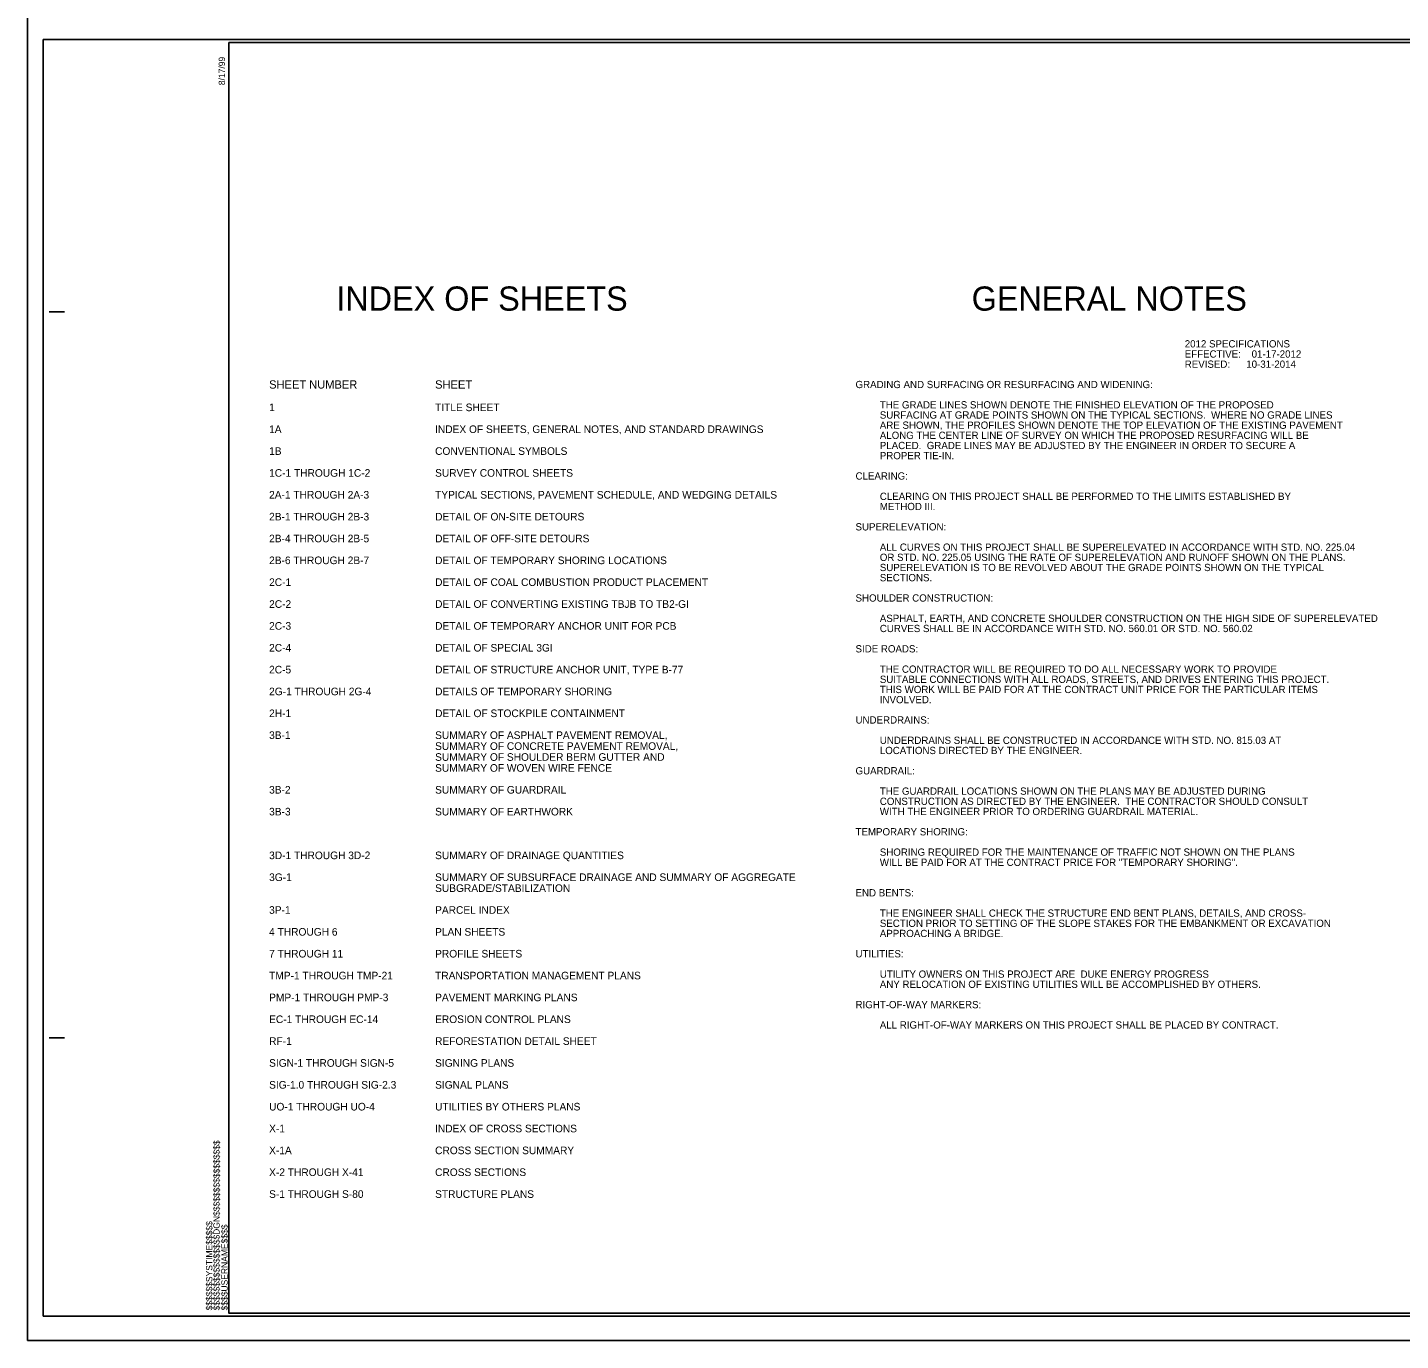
# Model space of a CAD drawing. Extents: x 2241278 to 2254132, y 649924 to 670434.
# Drawn here: x 2244559 to 2250231, y 649924 to 655349 of the extents above; entities that cross this region are included whole.
import ezdxf

# ---------------------------------------------------------------- set-up
doc = ezdxf.new("R2010")
doc.units = 0
for name, color, linetype in [('Sheet Cutting Line CELL', 7, 'Continuous'), ('Sheet Data Text CELL', 7, 'Continuous'), ('Sheet Plan CELL', 7, 'Continuous'), ('Sheet Plot Border Inside CELL', 7, 'Continuous'), ('Sheet Plot Border Outside CELL', 7, 'Continuous')]:
    doc.layers.add(name, color=color, linetype=linetype)

msp = doc.modelspace()

# ---------------------------------------------------------------- linework, layer by layer
at = {"layer": 'Sheet Cutting Line CELL'}
for p, q in [((2244558.8, 655399.2), (2244558.8, 649924.2)), ((2244558.8, 649924.2), (2252976.3, 649924.2))]:
    msp.add_line(p, q, dxfattribs=at)
at = {"layer": 'Sheet Plan CELL'}
for p, q in [((2245391.3, 655286.7), (2245391.3, 655286.7)), ((2244648.8, 654174.2), (2244711.3, 654174.2)), ((2244648.8, 651174.2), (2244711.3, 651174.2)), ((2245391.3, 650036.7), (2245391.3, 650036.7))]:
    msp.add_line(p, q, dxfattribs=at)
msp.add_lwpolyline([(2252891.3, 655286.7), (2245391.3, 655286.7), (2245391.3, 650036.7), (2252891.3, 650036.7)], close=True, dxfattribs=at)
at = {"layer": 'Sheet Plot Border Inside CELL'}
msp.add_lwpolyline([(2244623.8, 650024.2), (2252953.8, 650024.2), (2252953.8, 655299.2), (2244623.8, 655299.2)], close=True, dxfattribs=at)
at = {"layer": 'Sheet Plot Border Outside CELL'}
msp.add_lwpolyline([(2244558.8, 649924.2), (2252976.3, 649924.2), (2252976.3, 655399.2), (2244558.8, 655399.2)], close=True, dxfattribs=at)

# ---------------------------------------------------------------- texts
at = {"layer": 'Sheet Data Text CELL'}
for s, height, p in [('INDEX OF SHEETS', 100, (2245834.7, 654179.1)), ('GENERAL NOTES', 100, (2248459.5, 654179.1)), ('2012 SPECIFICATIONS', 30, (2249339.7, 654027.1)), ('EFFECTIVE:    01-17-2012', 30, (2249339.7, 653985.1)), ('REVISED:      10-31-2014', 30, (2249339.7, 653943.1)), ('SHEET NUMBER', 34.286, (2245557.1, 653857)), ('SHEET', 34.29, (2246242.8, 653857)), ('GRADING AND SURFACING OR RESURFACING AND WIDENING:  ', 30, (2247979.7, 653859.1)), ('         THE GRADE LINES SHOWN DENOTE THE FINISHED ELEVATION OF THE PROPOSED ', 30, (2247979.7, 653775.1)), ('1', 31.4, (2245557.1, 653763.9)), ('TITLE SHEET', 31.429, (2246242.8, 653763.9)), ('         SURFACING AT GRADE POINTS SHOWN ON THE TYPICAL SECTIONS.  WHERE NO GRADE LINES ', 30, (2247979.7, 653733.1)), ('1A', 31.43, (2245557.1, 653673.6)), ('INDEX OF SHEETS, GENERAL NOTES, AND STANDARD DRAWINGS', 31.429, (2246242.8, 653673.6)), ('         ARE SHOWN, THE PROFILES SHOWN DENOTE THE TOP ELEVATION OF THE EXISTING PAVEMENT ', 30, (2247979.7, 653691.1)), ('         ALONG THE CENTER LINE OF SURVEY ON WHICH THE PROPOSED RESURFACING WILL BE ', 30, (2247979.7, 653649.1)), ('         PLACED.  GRADE LINES MAY BE ADJUSTED BY THE ENGINEER IN ORDER TO SECURE A ', 30, (2247979.7, 653607.1)), ('1B', 31.43, (2245557.1, 653583.3)), ('CONVENTIONAL SYMBOLS', 31.429, (2246242.8, 653583.3)), ('         PROPER TIE-IN.  ', 30, (2247979.7, 653565.1)), ('1C-1 THROUGH 1C-2', 31.429, (2245557.1, 653493)), ('SURVEY CONTROL SHEETS', 31.429, (2246242.8, 653493)), ('CLEARING:  ', 30, (2247979.7, 653481.1)), ('2A-1 THROUGH 2A-3', 31.429, (2245557.1, 653402.7)), ('TYPICAL SECTIONS, PAVEMENT SCHEDULE, AND WEDGING DETAILS', 31.429, (2246242.8, 653402.7)), ('         CLEARING ON THIS PROJECT SHALL BE PERFORMED TO THE LIMITS ESTABLISHED BY ', 30, (2247979.7, 653397.1)), ('         METHOD III.', 30, (2247979.7, 653355.1)), ('2B-1 THROUGH 2B-3', 31.429, (2245557.1, 653312.4)), ('DETAIL OF ON-SITE DETOURS', 31.429, (2246242.8, 653312.4)), ('SUPERELEVATION:  ', 30, (2247979.7, 653271.1)), ('2B-4 THROUGH 2B-5', 31.429, (2245557.1, 653222.1)), ('DETAIL OF OFF-SITE DETOURS', 31.429, (2246242.8, 653222.1)), ('         ALL CURVES ON THIS PROJECT SHALL BE SUPERELEVATED IN ACCORDANCE WITH STD. NO. 225.04', 30, (2247979.7, 653187.1)), ('2B-6 THROUGH 2B-7', 31.429, (2245557.1, 653131.9)), ('DETAIL OF TEMPORARY SHORING LOCATIONS', 31.429, (2246242.8, 653131.9)), ('         SUPERELEVATION IS TO BE REVOLVED ABOUT THE GRADE POINTS SHOWN ON THE TYPICAL ', 30, (2247979.7, 653103.1)), ('         OR STD. NO. 225.05 USING THE RATE OF SUPERELEVATION AND RUNOFF SHOWN ON THE PLANS.', 30, (2247979.7, 653145.1)), ('2C-1', 31.43, (2245557.1, 653041.6)), ('DETAIL OF COAL COMBUSTION PRODUCT PLACEMENT', 31.429, (2246242.8, 653041.6)), ('         SECTIONS.  ', 30, (2247979.7, 653061.1)), ('2C-2', 31.43, (2245557.1, 652951.3)), ('DETAIL OF CONVERTING EXISTING TBJB TO TB2-GI', 31.429, (2246242.8, 652951.3)), ('SHOULDER CONSTRUCTION:  ', 30, (2247979.7, 652977.1)), ('         ASPHALT, EARTH, AND CONCRETE SHOULDER CONSTRUCTION ON THE HIGH SIDE OF SUPERELEVATED ', 30, (2247979.7, 652893.1)), ('2C-3', 31.43, (2245557.1, 652861)), ('DETAIL OF TEMPORARY ANCHOR UNIT FOR PCB', 31.429, (2246242.8, 652861)), ('         CURVES SHALL BE IN ACCORDANCE WITH STD. NO. 560.01 OR STD. NO. 560.02', 30, (2247979.7, 652851.1)), ('2C-4', 31.43, (2245557.1, 652770.7)), ('DETAIL OF SPECIAL 3GI', 31.429, (2246242.8, 652770.7)), ('SIDE ROADS:  ', 30, (2247979.7, 652767.1)), ('2C-5', 31.43, (2245557.1, 652680.4)), ('DETAIL OF STRUCTURE ANCHOR UNIT, TYPE B-77', 31.429, (2246242.8, 652680.4)), ('         THE CONTRACTOR WILL BE REQUIRED TO DO ALL NECESSARY WORK TO PROVIDE ', 30, (2247979.7, 652683.1)), ('         SUITABLE CONNECTIONS WITH ALL ROADS, STREETS, AND DRIVES ENTERING THIS PROJECT.  ', 30, (2247979.7, 652641.1)), ('2G-1 THROUGH 2G-4', 31.429, (2245557.1, 652590.1)), ('DETAILS OF TEMPORARY SHORING', 31.429, (2246242.8, 652590.1)), ('         THIS WORK WILL BE PAID FOR AT THE CONTRACT UNIT PRICE FOR THE PARTICULAR ITEMS ', 30, (2247979.7, 652599.1)), ('         INVOLVED.  ', 30, (2247979.7, 652557.1)), ('2H-1', 31.43, (2245557.1, 652499.9)), ('DETAIL OF STOCKPILE CONTAINMENT', 31.429, (2246242.8, 652499.9)), ('UNDERDRAINS:  ', 30, (2247979.7, 652473.1)), ('3B-1', 31.43, (2245557.1, 652409.6)), ('SUMMARY OF ASPHALT PAVEMENT REMOVAL,', 31.429, (2246242.8, 652409.6)), ('SUMMARY OF CONCRETE PAVEMENT REMOVAL,', 31.429, (2246242.8, 652364.4)), ('         UNDERDRAINS SHALL BE CONSTRUCTED IN ACCORDANCE WITH STD. NO. 815.03 AT ', 30, (2247979.7, 652389.1)), ('SUMMARY OF SHOULDER BERM GUTTER AND', 31.429, (2246242.8, 652319.3)), ('         LOCATIONS DIRECTED BY THE ENGINEER.  ', 30, (2247979.7, 652347.1)), ('SUMMARY OF WOVEN WIRE FENCE', 31.429, (2246242.8, 652274.1)), ('GUARDRAIL:  ', 30, (2247979.7, 652263.1)), ('3B-2', 31.43, (2245557.1, 652183.9)), ('SUMMARY OF GUARDRAIL', 31.429, (2246242.8, 652183.9)), ('         THE GUARDRAIL LOCATIONS SHOWN ON THE PLANS MAY BE ADJUSTED DURING ', 30, (2247979.7, 652179.1)), ('         CONSTRUCTION AS DIRECTED BY THE ENGINEER.  THE CONTRACTOR SHOULD CONSULT', 30, (2247979.7, 652137.1)), ('3B-3', 31.43, (2245557.1, 652093.6)), ('SUMMARY OF EARTHWORK', 31.429, (2246242.8, 652093.6)), ('         WITH THE ENGINEER PRIOR TO ORDERING GUARDRAIL MATERIAL.', 30, (2247979.7, 652095.1)), ('TEMPORARY SHORING:  ', 30, (2247979.7, 652011.1)), ('3D-1 THROUGH 3D-2', 31.429, (2245557.1, 651913)), ('SUMMARY OF DRAINAGE QUANTITIES', 31.429, (2246242.8, 651913)), ('         SHORING REQUIRED FOR THE MAINTENANCE OF TRAFFIC NOT SHOWN ON THE PLANS ', 30, (2247979.7, 651927.1)), ('         WILL BE PAID FOR AT THE CONTRACT PRICE FOR "TEMPORARY SHORING".', 30, (2247979.7, 651885.1)), ('3G-1', 31.43, (2245557.1, 651822.7)), ('SUMMARY OF SUBSURFACE DRAINAGE AND SUMMARY OF AGGREGATE', 31.429, (2246242.8, 651822.7)), ('SUBGRADE/STABILIZATION', 31.429, (2246242.8, 651777.6)), ('END BENTS:  ', 30, (2247979.7, 651759.1)), ('3P-1', 31.43, (2245557.1, 651687.3)), ('PARCEL INDEX', 31.429, (2246242.8, 651687.3)), ('         THE ENGINEER SHALL CHECK THE STRUCTURE END BENT PLANS, DETAILS, AND CROSS-', 30, (2247979.7, 651675.1)), ('         SECTION PRIOR TO SETTING OF THE SLOPE STAKES FOR THE EMBANKMENT OR EXCAVATION ', 30, (2247979.7, 651633.1)), ('4 THROUGH 6', 31.429, (2245557.1, 651597)), ('PLAN SHEETS', 31.429, (2246242.8, 651597)), ('         APPROACHING A BRIDGE.  ', 30, (2247979.7, 651591.1)), ('7 THROUGH 11 ', 31.429, (2245557.1, 651506.7)), ('PROFILE SHEETS', 31.429, (2246242.8, 651506.7)), ('UTILITIES:  ', 30, (2247979.7, 651507.1)), ('TMP-1 THROUGH TMP-21', 31.429, (2245557.1, 651416.4)), ('TRANSPORTATION MANAGEMENT PLANS', 31.429, (2246242.8, 651416.4)), ('         UTILITY OWNERS ON THIS PROJECT ARE  DUKE ENERGY PROGRESS', 30, (2247979.7, 651423.1)), ('         ANY RELOCATION OF EXISTING UTILITIES WILL BE ACCOMPLISHED BY OTHERS.  ', 30, (2247979.7, 651381.1)), ('PMP-1 THROUGH PMP-3', 31.429, (2245557.1, 651326.1)), ('PAVEMENT MARKING PLANS', 31.429, (2246242.8, 651326.1)), ('RIGHT-OF-WAY MARKERS:  ', 30, (2247979.7, 651297.1)), ('EC-1 THROUGH EC-14', 31.429, (2245557.1, 651235.9)), ('EROSION CONTROL PLANS', 31.429, (2246242.8, 651235.9)), ('         ALL RIGHT-OF-WAY MARKERS ON THIS PROJECT SHALL BE PLACED BY CONTRACT.  ', 30, (2247979.7, 651213.1)), ('RF-1', 31.43, (2245557.1, 651145.6)), ('REFORESTATION DETAIL SHEET', 31.429, (2246242.8, 651145.6)), ('SIGN-1 THROUGH SIGN-5', 31.429, (2245557.1, 651055.3)), ('SIGNING PLANS', 31.429, (2246242.8, 651055.3)), ('SIG-1.0 THROUGH SIG-2.3', 31.429, (2245557.1, 650965)), ('SIGNAL PLANS', 31.429, (2246242.8, 650965)), ('UO-1 THROUGH UO-4', 31.429, (2245557.1, 650874.7)), ('UTILITIES BY OTHERS PLANS', 31.429, (2246242.8, 650874.7)), ('X-1', 31.43, (2245557.1, 650784.4)), ('INDEX OF CROSS SECTIONS', 31.429, (2246242.8, 650784.4)), ('X-1A', 31.43, (2245557.1, 650694.1)), ('CROSS SECTION SUMMARY', 31.429, (2246242.8, 650694.1)), ('X-2 THROUGH X-41', 31.429, (2245557.1, 650603.9)), ('CROSS SECTIONS', 31.429, (2246242.8, 650603.9)), ('S-1 THROUGH S-80', 31.429, (2245557.1, 650513.6)), ('STRUCTURE PLANS', 31.429, (2246242.8, 650513.6))]:
    msp.add_text(s, height=height, dxfattribs=at).set_placement(p)
at = {"layer": 'Sheet Plan CELL'}
for s, p in [('8/17/99', (2245375, 655110.7)), ('$$$$$$$$$$$$$$$$DGN$$$$$$$$$$$$$$$$', (2245353, 650048.5)), ('$$$$$$SYSTIME$$$$$', (2245322.8, 650048.5)), ('$$$$USERNAME$$$$', (2245385.9, 650048.5))]:
    msp.add_text(s, height=26.25, rotation=90, dxfattribs=at).set_placement(p)

doc.saveas('drawing.dxf')
